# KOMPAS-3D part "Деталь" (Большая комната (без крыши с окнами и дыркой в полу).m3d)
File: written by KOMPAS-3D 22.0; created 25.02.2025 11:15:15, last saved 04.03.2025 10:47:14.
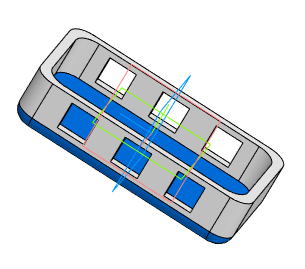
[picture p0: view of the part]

Document properties: Автор: Пользователь Windows; Полное имя файла: C:\Users\Student\Documents\Картошечка\База Сабнатика\Большая комната\Большая комната (без крыши с окнами и дыркой в полу).m3d

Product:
- Part/product: Деталь
    Масса: 0.670424

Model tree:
1. Эскиз:1
2. Элемент выдавливания:1
     Расстояние 1 = 35
3. Скругление:2  (with: Элемент выдавливания:1)
     Радиус = 10
4. Скругление:1  (with: Элемент выдавливания:1)
     Радиус = 7
5. Эскиз:3  (with: Элемент выдавливания:1)
6. Элемент выдавливания:2
     Расстояние 2 = 7
7. Эскиз:4  (with: Элемент выдавливания:2)
8. Элемент выдавливания:3
     Расстояние 2 = 21
9. Эскиз:5  (with: Элемент выдавливания:1, Элемент выдавливания:2)
10. Элемент выдавливания:4
     Расстояние 2 = 70
11. Эскиз:8  (with: Элемент выдавливания:3)
12. Элемент выдавливания:7
     Расстояние 2 = 7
